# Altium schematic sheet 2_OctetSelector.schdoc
size 309 x 223 mm; Symbol: Sheet-Symbol_A4; Device: Sheet-Symbol_A4; @Project Name: V2 - ODrive Rev Motor Module; @Page Count: 5; @Update Date: 2024-12-06; @Create Date: 2024-12-05; @Schematic Name: Schematic-A; @Page No: 2; @Page Name: OctetSelector; Company: EasyEDA.com; Reviewed: EasyEDA; Version: V0.1; Page Size: A4; Part Number: JLCPCB-002; Drawn: EasyEDA; @Board Name: BaseModule; @Create Time: 01:02:26; @Update Time: 18:05:14
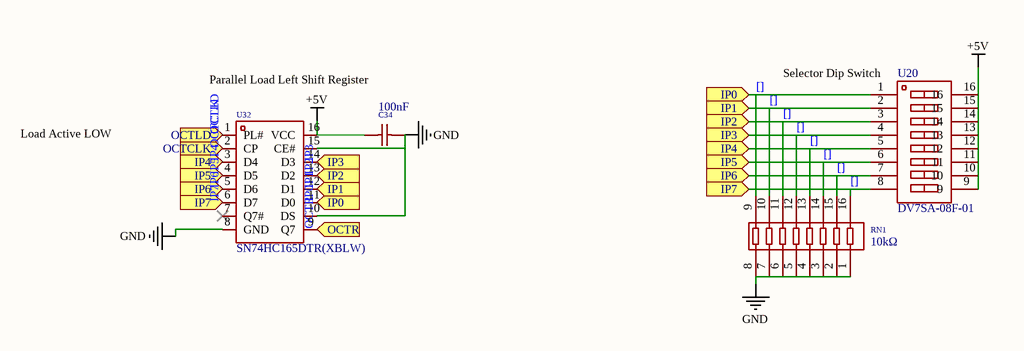
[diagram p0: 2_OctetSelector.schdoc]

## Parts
C34  100nF  [C0805]
RN1  10kΩ  [RES-ARRAY-SMD_16P-L3.8-W1.6-P0.50-BL]
U20  DV7SA-08F-01  [SW-SMD_DV7SA-08F-01]
U32  SN74HC165DTR(XBLW)  [SOP-16_L9.9-W3.9-P1.27-LS6.0-BL]

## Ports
IP0 (in), IP1 (in), IP2 (in), IP3 (in), IP4 (in), IP5 (in), IP6 (in), IP7 (in), OCTCLK (in), OCTLD (in), OCTR (in)

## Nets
+5V: C34.2 U20.9 U20.10 U20.11 U20.12 U20.13 U20.14 U20.15 U20.16 U32.16(VCC)
GND: C34.1 RN1.1 RN1.2 RN1.3 RN1.4 RN1.5 RN1.6 RN1.7 RN1.8 U32.8(GND) U32.10(DS) U32.15(CE#)
[]: RN1.9 RN1.10 RN1.11 RN1.12 RN1.13 RN1.14 RN1.15 RN1.16 U20.1 U20.2 U20.3 U20.4 U20.5 U20.6 U20.7 U20.8 U32.3(D4) U32.4(D5) U32.5(D6) U32.6(D7) U32.11(D0) U32.12(D1) U32.13(D2) U32.14(D3) ; port IP0, port IP1, port IP2, port IP3, port IP4, port IP5, port IP6, port IP7  [also labelled IP0, IP1, IP2, IP3, IP4, IP5, IP6, IP7]
OCTCLK: U32.2(CP) ; port OCTCLK
OCTLD: U32.1(PL#) ; port OCTLD
OCTR: U32.9(Q7) ; port OCTR

Not connected (* = marked no-connect by the designer): U32 7(Q7#)*

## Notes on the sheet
- Load Active LOW
- Parallel Load Left Shift Register
- (near U20) Selector Dip Switch

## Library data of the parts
C34 = 0805B104K500NT: Manufacturer: FH(风华); Add into BOM: yes; Tolerance: ±10%
RN1 = EXB2HV103JV: Manufacturer: PANASONIC(松下); Add into BOM: yes; Tolerance: ±5%; Temperature Coefficient: ±200ppm/℃
U20 = DV7SA-08F-01: Manufacturer: G-Switch(品赞); Add into BOM: yes; Circuit: SPST; Number of Positions: 8-bit
U32 = SN74HC165DTR(XBLW): Manufacturer: XBLW(芯伯乐); Add into BOM: yes; Supply Voltage: 2V~6V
